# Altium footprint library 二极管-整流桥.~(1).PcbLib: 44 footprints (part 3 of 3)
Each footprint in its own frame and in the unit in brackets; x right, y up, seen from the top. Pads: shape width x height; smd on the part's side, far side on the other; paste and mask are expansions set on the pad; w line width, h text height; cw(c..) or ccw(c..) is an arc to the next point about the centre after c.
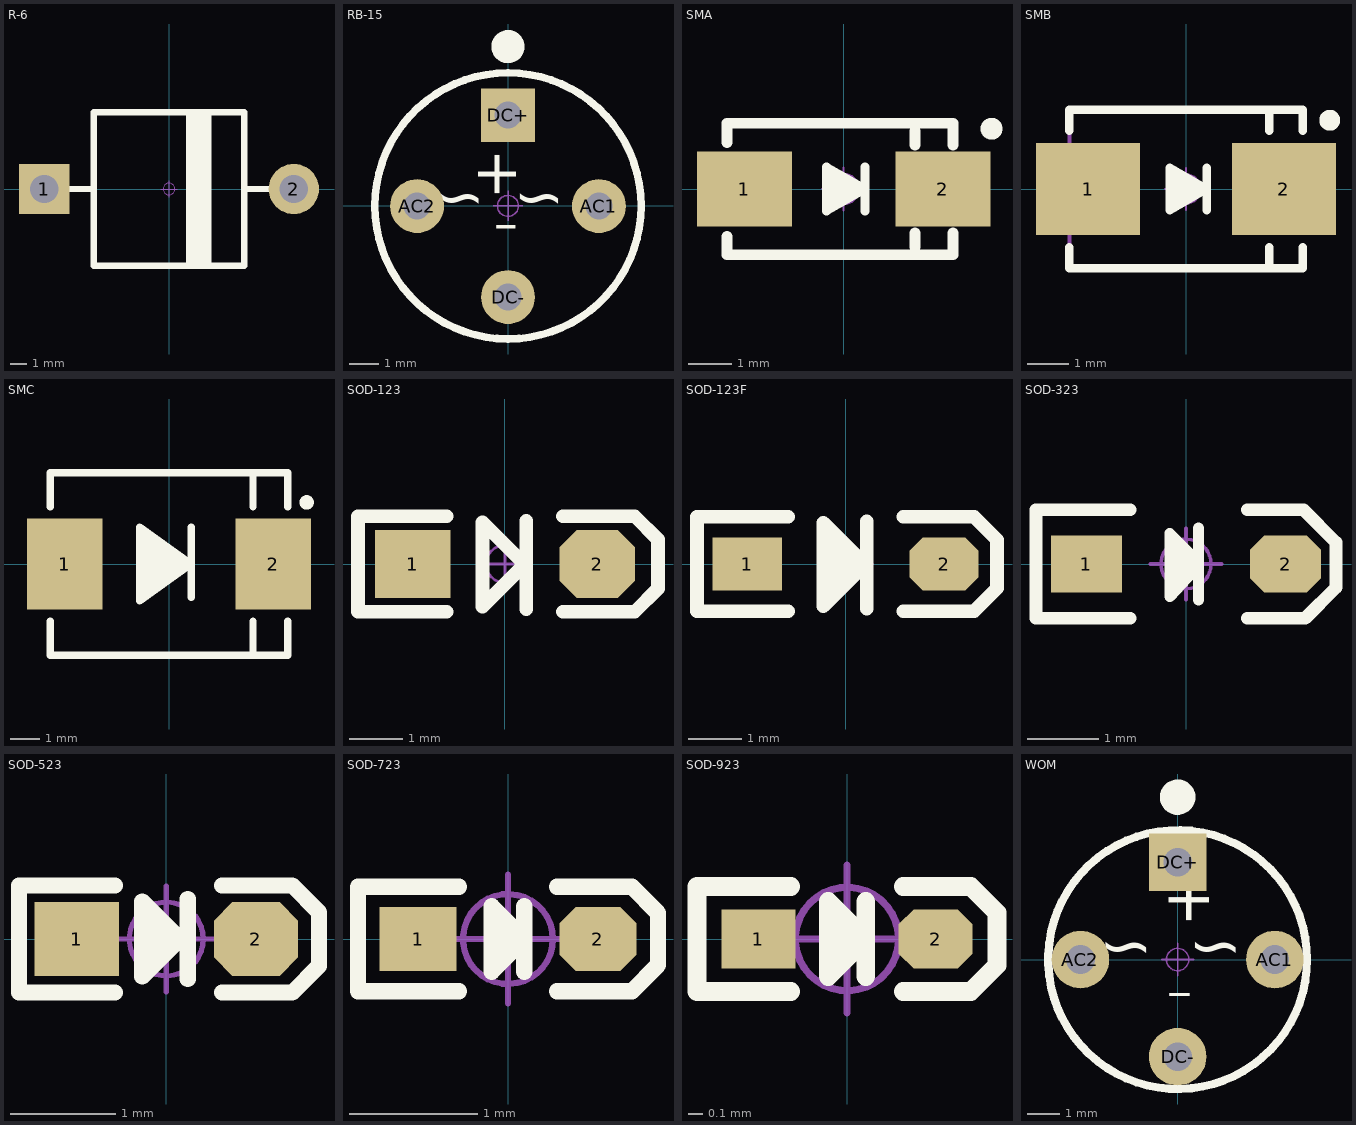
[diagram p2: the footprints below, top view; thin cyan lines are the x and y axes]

## R-6 [mm] "8.8*14.9mm(直径，脚距）"
pads (2):
  rect 3x3 hole 1.7: 1(-7.45,0)
  round 3 hole 1.7: 2(7.45,0)
Top Overlay:
  rectangle: 1.016,-4.572 2.54,4.572
  lines w0.381: -6.056,0 -4.5,0 ; 4.5,0 6.024,0 ; -4.5,-4.572 4.5,-4.572 4.5,4.572 -4.5,4.572 -4.5,-4.572
Mechanical 15:
  circle w0.05: c0,0 r0.35
  lines w0.05: -0.5,0 0.5,0 ; 0,-0.5 0,0.5
3D body: height 8.85, standoff -3.45, extent -8.1,-4.401 8.1,4.401

## RB-15 [mm] "8.9*3.5mm(直径，高)"
pads (4):
  round 1.8 hole 0.9: AC1(3.041,-0.007) AC2(-3.041,-0.007) DC-(0,-3.048)
  rect 1.8x1.8 hole 0.9: DC+(0,3.033)
Top Overlay:
  circle w0.254: c0,0 r4.45
  circle w0.6: c0,5.327 r0.254
  text "+" at 0.762,1.905 h2.54
  text "-" at 0.381,-1.905 h3.05
  text "~" at -0.762,-0.889 h2.54
  text "~" at 1.905,-0.889 h2.54
Mechanical 15:
  circle w0.05: c0,0 r0.35
  lines w0.05: -0.5,0 0.5,0 ; 0,-0.5 0,0.5
3D body: height 3.55, standoff -3.45, extent -4.45,-4.45 4.45,4.45

## SMA [mm] "4.5x2.6*2.2mm（长宽高，不包括引脚）"
height 2.54
pads (2):
  rect 2.2x1.75 smd: 1(-2.3,0) 2(2.3,0)
Top Overlay:
  circle w0.254: c3.429,1.397 r0.127
  lines w0.203: 0.494,-0.508 0.494,0.508 ; -0.395,-0.508 0.494,0 -0.395,0.508 -0.395,-0.508
  lines w0.254: -2.7,-1.105 -2.7,-1.524 2.54,-1.524 2.54,-1.016 ; -2.7,1.08 -2.7,1.524 2.54,1.524 2.54,1.016 ; -0.33,0.305 0.305,0 -0.254,-0.305 -0.254,0.051 0.023,0 ; 1.651,-1.35 1.651,-1.016 ; 1.651,1.016 1.651,1.35
Mechanical 15:
  circle w0.05: c0,0 r0.35
  lines w0.05: -0.5,0 0.5,0 ; 0,-0.5 0,0.5
3D body: height 2.15, standoff 0.04, extent -2.528,-1.3 2.575,1.3

## SMB [mm] "4.7*3.9*2.2mm(长宽高，不包括引脚）"
height 2.4
pads (2):
  rect 2.5x2.2 smd: 1(-2.35,0) 2(2.35,0)
Top Overlay:
  circle w0.25: c3.45,1.65 r0.125
  lines w0.2: -2.8,-1.4 -2.8,-1.9 2.8,-1.9 2.8,-1.4 ; -2.8,1.4 -2.8,1.9 2.8,1.9 2.8,1.4 ; 2,-1.9 2,-1.4 ; 2,1.4 2,1.9
  lines w0.203: 0.5,-0.508 0.5,0.508 ; -0.389,-0.508 -0.389,0.508 0.5,0 -0.389,-0.508
  lines w0.254: -0.254,0 0.279,0 ; 0.279,0 -0.229,0.279 -0.229,-0.305 0.279,0
Mechanical 13:
  lines w0.1: 2.8,-1.9 -2.8,-1.9 -2.8,1.9 2.8,1.9
Mechanical 15:
  circle w0.05: c0,0 r0.35
  lines w0.05: -0.5,0 0.5,0 ; 0,-0.5 0,0.5
3D body: height 2.35, standoff 0.04, extent -2.629,-1.8 2.675,1.8

## SMC [mm] "7.1x5.9*2.3mm（长宽高，不包括引脚）"
height 2.41
pads (2):
  rect 2.6x3.15 smd: 1(-3.6,0) 2(3.6,0)
Top Overlay:
  circle w0.25: c4.75,2.125 r0.125
  lines w0.254: -4.1,-1.975 -4.1,-3.15 4.1,-3.15 4.1,-1.975 ; -4.1,1.975 -4.1,3.15 4.1,3.15 4.1,1.975 ; -0.889,0.991 0.5,0 -0.889,-0.965 -0.914,0.762 0.229,0 -0.711,-0.66 -0.762,0.483 0,-0.051 -0.584,-0.33 -0.635,0.152 -0.229,-0.051 -0.737,-0.127 ; 0.762,-1.143 0.762,1.27 ; 2.9,-3.15 2.9,-1.975 ; 2.9,1.975 2.9,3.15 ; -1.016,-1.27 0.762,0 -1.016,1.27 -1.016,-1.27
Mechanical 13:
  lines w0.1: -4.065,-3.11 4.065,-3.11 ; -4.065,3.11 4.065,3.11
Mechanical 15:
  circle w0.05: c0,0 r0.35
  lines w0.05: -0.5,0 0.5,0 ; 0,-0.5 0,0.5
3D body: height 2.45, standoff 0.03, extent -3.953,-2.9 3.953,2.9

## SOD-123 [mil] "2.7x1.6X1.1mm（长宽高，不包括引脚）"
pads (2):
  rect 55x50 smd: 1(-67.5,0)
  oct 55x50 smd: 2(67.5,0)
Top Overlay:
  lines w10: -42.5,-35 -107.5,-35 -107.5,35 -42.5,35 ; 14,-0.8 -16.4,-31.2 -16.4,30.5 15.6,-1.5 ; 15.6,-33.1 15.6,31.7 ; 42.5,-35 95,-35 112,-18 112,18 95,35 42.5,35
Mechanical 15:
  circle w1.97: c0,0 r13.78
  lines w1.97: -19.68,0 19.68,0 ; 0,-19.68 0,19.68
3D body: height 48.03, standoff 0, extent -72.84,-31.5 72.83,31.5

## SOD-123F [mm] "2.7x1.6X1.1mm（长宽高，不包括引脚）"
pads (2):
  rect 1.3x1 smd: 1(-1.85,0)
  oct 1.3x1 smd: 2(1.85,0)
Top Overlay:
  lines w0.254: -1.079,-0.889 -2.794,-0.889 -2.794,0.889 -1.079,0.889 ; -0.254,0.559 -0.229,-0.432 0.254,0 0,0.254 0,0 0,-0.254 ; 0.356,-0.02 -0.417,-0.792 -0.417,0.775 0.396,-0.038 ; 0.396,-0.841 0.396,0.805 ; 1.079,-0.889 2.413,-0.889 2.845,-0.457 2.845,0.457 2.413,0.889 1.079,0.889
Mechanical 15:
  circle w0.05: c0,0 r0.35
  lines w0.05: -0.5,0 0.5,0 ; 0,-0.5 0,0.5
3D body: height 1.15, standoff 0.04, extent -1.9,-0.8 1.9,0.8

## SOD-323 [mm] "1.8x1.3X0.9mm（长宽高，不包括引脚）"
pads (2):
  rect 1x0.8 smd: 1(-1.4,0)
  oct 1x0.8 smd: 2(1.4,0)
Top Overlay:
  lines w0.152: 0.178,-0.508 0.178,0.508 ; 0.178,-0.025 -0.229,-0.457 -0.229,0.432 0.178,0.025
  lines w0.178: -0.787,-0.762 -2.108,-0.762 -2.108,0.762 -0.787,0.762 ; 0.864,-0.762 1.676,-0.762 2.108,-0.33 2.108,0.305 1.651,0.762 0.864,0.762
  lines w0.254: -0.127,0.254 -0.152,-0.178 0.025,-0.025 -0.025,0.127
Mechanical 15:
  circle w0.05: c0,0 r0.35
  lines w0.05: -0.5,0 0.5,0 ; 0,-0.5 0,0.5
3D body: height 1, standoff 0.04, extent -1.337,-0.631 1.311,0.669

## SOD-523 [mm] "1.2x0.8X0.6mm（长宽高，不包括引脚）"
pads (2):
  rect 0.8x0.7 smd: 1(-0.85,0)
  oct 0.8x0.7 smd: 2(0.85,0)
Top Overlay:
  rectangle: -0.178,-0.178 0,0.178
  lines w0.152: -0.488,-0.508 -1.397,-0.508 -1.397,0.508 -0.488,0.508 ; -0.127,0 0.127,0 ; 0.203,-0.381 0.203,0.381 ; 0.528,-0.508 1.194,-0.508 1.448,-0.254 1.448,0.254 1.194,0.508 0.528,0.508 ; 0.127,0 -0.229,0.356 -0.229,-0.356 0.127,0
Mechanical 15:
  circle w0.05: c0,0 r0.35
  lines w0.05: -0.5,0 0.5,0 ; 0,-0.5 0,0.5
3D body: height 0.65, standoff 0.05, extent -0.8,-0.4 0.8,0.4

## SOD-723 [mm] "1x0.6X0.5mm（长宽高，不包括引脚）"
pads (2):
  rect 0.6x0.5 smd: 1(-0.7,0)
  oct 0.6x0.5 smd: 2(0.7,0)
Top Overlay:
  lines w0.127: -0.381,-0.406 -1.168,-0.406 -1.168,0.406 -0.381,0.406 ; 0,-0.127 0,0.127 -0.127,0.254 ; 0.127,-0.254 0.127,0.254 ; 0.381,-0.406 0.965,-0.406 1.168,-0.203 1.168,0.203 0.965,0.406 0.381,0.406 ; -0.127,0.254 -0.127,-0.254 0.127,0 -0.127,0.254
Mechanical 15:
  circle w0.05: c0,0 r0.35
  lines w0.05: -0.5,0 0.5,0 ; 0,-0.5 0,0.5
3D body: height 0.53, standoff 0.03, extent -0.7,-0.3 0.7,0.3

## SOD-923 [mm] "0.8x0.6X0.4mm（长宽高，不包括引脚）"
pads (2):
  rect 0.5x0.4 smd: 1(-0.6,0)
  oct 0.5x0.4 smd: 2(0.6,0)
Top Overlay:
  lines w0.127: -0.381,-0.356 -1.016,-0.356 -1.016,0.356 -0.381,0.356 ; 0,-0.127 0,0.127 -0.127,0.254 ; 0.127,-0.254 0.127,0.254 ; 0.381,-0.356 0.838,-0.356 1.016,-0.178 1.016,0.178 0.838,0.356 0.381,0.356 ; -0.127,0.254 0.127,0 -0.127,-0.254 -0.127,0.254
Mechanical 15:
  circle w0.05: c0,0 r0.35
  lines w0.05: -0.5,0 0.5,0 ; 0,-0.5 0,0.5
3D body: height 0.43, standoff 0.03, extent -0.5,-0.3 0.5,0.3

## WOM [mm] "8.1*5.1mm(直径，高)"
pads (4):
  round 1.8 hole 0.9: AC1(3.04,0) AC2(-3.04,0) DC-(0,-3.04)
  rect 1.8x1.8 hole 0.9: DC+(0,3.04)
Top Overlay:
  circle w0.6: c0,5.08 r0.254
  circle w0.254: c0,0 r4.05
  text "+" at -0.762,1.016 h2.54
  text "-" at 0.508,-2.286 h3.05
  text "~" at 2.032,-0.762 h2.54
  text "~" at -0.762,-0.762 h2.54
Mechanical 15:
  circle w0.05: c0,0 r0.35
  lines w0.05: -0.5,0 0.5,0 ; 0,-0.5 0,0.5
3D body: height 5.1, standoff -3.5, extent -4.05,-4.05 4.05,4.05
